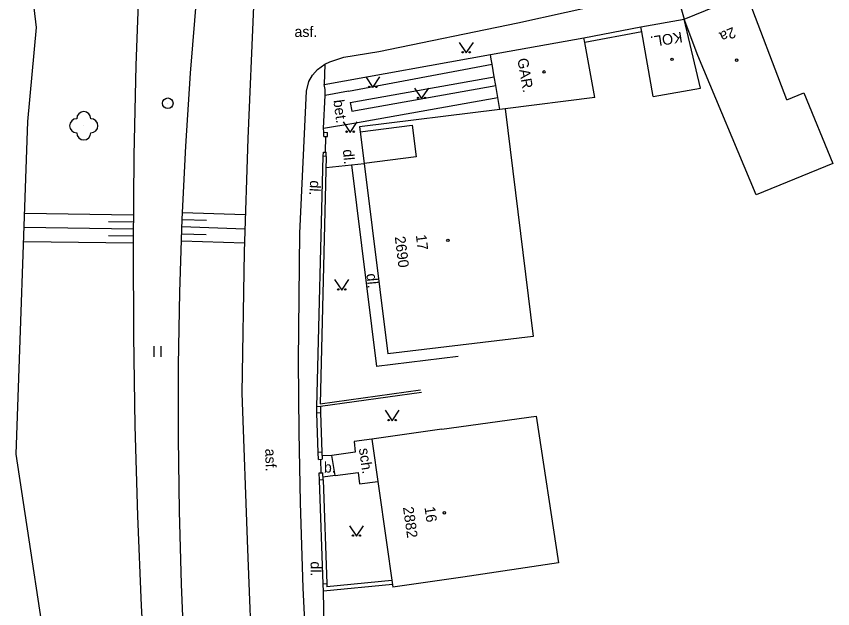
# Model space of a CAD drawing. Extents: x -584400 to -581602, y -1210894 to -1208793.
# Drawn here: x -583351.4 to -583293.7, y -1209655.4 to -1209613.5 of the extents above; entities that cross this region are included whole.
import ezdxf

# ---------------------------------------------------------------- set-up
doc = ezdxf.new("R2010")
doc.units = 0
for name, color, linetype in [('BUDOVY_MĚŘ', 7, 'Continuous'), ('BUDOVY_NEMĚŘ', 7, 'Continuous'), ('MAP_ZN_BP', 7, 'Continuous'), ('POMOC_POPIS', 7, 'Continuous'), ('ROZHRANÍ_PLOCH', 7, 'Continuous'), ('VÝŠKOPIS', 7, 'Continuous'), ('ZELEŇ', 7, 'Continuous'), ('ZN_BUDOV', 7, 'Continuous'), ('ZN_DOPLŇKOVÉ', 7, 'Continuous'), ('ZN_KULTUR', 7, 'Continuous'), ('Č_POPIS_EVID', 7, 'Continuous'), ('Č_POPIS_ORIENT', 7, 'Continuous')]:
    doc.layers.add(name, color=color, linetype=linetype)

msp = doc.modelspace()

# ---------------------------------------------------------------- linework, layer by layer
at = {"layer": 'BUDOVY_MĚŘ'}
for points in [[(-583304.16, -1209613.75), (-583299.75, -1209611.92)], [(-583306.36, -1209619.21), (-583307.16, -1209614.63), (-583307.22, -1209614.28), (-583304.16, -1209613.75)], [(-583303.19, -1209616.31), (-583304.16, -1209613.75)], [(-583317.19, -1209620.13), (-583317.34, -1209619.28), (-583317.49, -1209618.43), (-583317.6, -1209617.82), (-583317.74, -1209616.93), (-583317.8, -1209616.57), (-583317.86, -1209616.23), (-583311.25, -1209615.05)], [(-583310.49, -1209619.29), (-583311.19, -1209615.39), (-583311.25, -1209615.05)], [(-583310.49, -1209619.29), (-583316.82, -1209620.08), (-583317.19, -1209620.13)], [(-583317.19, -1209620.13), (-583327.11, -1209621.36), (-583327.07, -1209621.7), (-583326.79, -1209623.95), (-583325.12, -1209637.42)], [(-583316.82, -1209620.08), (-583314.84, -1209636.19), (-583325.12, -1209637.42)], [(-583327.07, -1209621.7), (-583323.4, -1209621.25), (-583323.12, -1209623.49), (-583326.79, -1209623.95)], [(-583321.3, -1209642.75), (-583326.25, -1209643.46), (-583324.76, -1209653.91)], [(-583319.81, -1209653.21), (-583324.76, -1209653.91)]]:
    msp.add_lwpolyline(points, dxfattribs=at)
at = {"layer": 'BUDOVY_NEMĚŘ'}
for points in [[(-583296.91, -1209619.44), (-583299.75, -1209611.92)], [(-583306.36, -1209619.21), (-583303.01, -1209618.63), (-583304.16, -1209613.75)], [(-583296.91, -1209619.44), (-583295.71, -1209618.95), (-583293.66, -1209623.95), (-583299.07, -1209626.16), (-583303.19, -1209616.31)], [(-583321.3, -1209642.75), (-583314.62, -1209641.83), (-583313.06, -1209652.19), (-583319.81, -1209653.21)]]:
    msp.add_lwpolyline(points, dxfattribs=at)
at = {"layer": 'MAP_ZN_BP'}
for radius in [0.375, 0.0005]:
    msp.add_circle((-583340.68, -1209619.691), radius, dxfattribs=at)
at = {"layer": 'ROZHRANÍ_PLOCH'}
for points in [[(-583322.44, -1209546.69), (-583325.37, -1209557.92), (-583329.4, -1209574.45), (-583329.82, -1209576.82), (-583331.22, -1209584.38), (-583332.92, -1209596.23), (-583333.98, -1209605.2), (-583334.42, -1209609.19), (-583334.48, -1209610.2), (-583334.58, -1209612.13), (-583335.13, -1209612.11), (-583335.13, -1209612.8), (-583334.62, -1209612.84), (-583335.02, -1209622.17), (-583335.28, -1209630.19), (-583335.44, -1209640.2), (-583335.04, -1209651.23), (-583334.69, -1209660.24)], [(-583348.69, -1209662.39), (-583351.39, -1209644.52), (-583350.57, -1209620.97), (-583349.96, -1209614.34), (-583351.26, -1209603.38), (-583349.77, -1209592.11), (-583348.74, -1209577.52), (-583341.06, -1209559.52)], [(-583329.58, -1209616.92), (-583329.21, -1209616.76), (-583328.23, -1209616.43), (-583325.75, -1209616.02), (-583315.92, -1209614), (-583309.09, -1209612.5), (-583304.81, -1209611.5), (-583304.16, -1209613.75)], [(-583330.81, -1209660.07), (-583331.11, -1209653.98), (-583331.29, -1209647.94), (-583331.4, -1209642.95), (-583331.44, -1209637.9), (-583331.33, -1209628.88), (-583330.87, -1209618.83), (-583330.71, -1209618.16), (-583330.45, -1209617.69), (-583330.1, -1209617.29), (-583329.58, -1209616.92)], [(-583329.58, -1209616.92), (-583329.61, -1209618.37)], [(-583327.89, -1209618.84), (-583317.74, -1209616.93)], [(-583327.78, -1209619.63), (-583317.6, -1209617.82)], [(-583327.89, -1209618.84), (-583329.56, -1209619.15), (-583329.54, -1209618.71)], [(-583327.78, -1209619.63), (-583327.66, -1209620.24), (-583317.49, -1209618.43)], [(-583329.67, -1209621.46), (-583329.56, -1209619.15)], [(-583329.67, -1209621.46), (-583327.52, -1209621.09), (-583317.34, -1209619.28)], [(-583329.64, -1209621.74), (-583329.67, -1209621.46)], [(-583329.49, -1209624.23), (-583327.68, -1209624.04)], [(-583327.68, -1209624.04), (-583326.79, -1209623.95)], [(-583327.68, -1209624.04), (-583325.91, -1209638.32)], [(-583320.14, -1209637.6), (-583325.91, -1209638.32)], [(-583329.07, -1209644.61), (-583329.77, -1209644.63)], [(-583328.84, -1209646.01), (-583329.07, -1209644.61)], [(-583328.84, -1209646.01), (-583329.71, -1209646.13)], [(-583329.62, -1209656.67), (-583329.66, -1209654.21)]]:
    msp.add_lwpolyline(points, dxfattribs=at)
at = {"layer": 'VÝŠKOPIS'}
for points in [[(-583342.71, -1209610.64), (-583342.93, -1209617.01), (-583343.07, -1209623.39), (-583343.13, -1209629.76), (-583343.11, -1209636.14), (-583343, -1209642.51), (-583342.82, -1209648.88), (-583342.56, -1209655.25), (-583342.04, -1209664.4)], [(-583339.18, -1209664.02), (-583339.49, -1209658.86), (-583339.72, -1209653.7), (-583339.86, -1209648.54), (-583339.93, -1209643.37), (-583339.92, -1209638.21), (-583339.83, -1209633.05), (-583339.66, -1209627.88), (-583339.41, -1209622.72), (-583339.07, -1209617.57), (-583338.61, -1209611.81)], [(-583350.8, -1209627.46), (-583343.12, -1209627.57)], [(-583335.2, -1209627.59), (-583339.64, -1209627.44)], [(-583344.86, -1209628.05), (-583343.12, -1209628.07)], [(-583337.94, -1209627.99), (-583339.66, -1209627.94)], [(-583350.83, -1209628.46), (-583343.12, -1209628.57)], [(-583335.23, -1209628.59), (-583339.68, -1209628.44)], [(-583344.88, -1209629.05), (-583343.13, -1209629.07)], [(-583337.96, -1209628.99), (-583339.7, -1209628.94)], [(-583350.87, -1209629.46), (-583343.13, -1209629.57)], [(-583335.26, -1209629.59), (-583339.72, -1209629.44)]]:
    msp.add_lwpolyline(points, dxfattribs=at)
at = {"layer": 'ZELEŇ'}
msp.add_circle((-583346.62, -1209621.28), 0.0005, dxfattribs=at)
for centre, start, end in [((-583346.62, -1209620.78), 0, 179.99999), ((-583347.12, -1209621.28), 89.99999, 269.99999), ((-583346.12, -1209621.28), 270, 89.99999), ((-583346.62, -1209621.78), 179.99999, 359.99999)]:
    msp.add_arc(centre, 0.5, start, end, dxfattribs=at)
at = {"layer": 'ZN_BUDOV'}
for centre in [(-583305.02, -1209616.58), (-583300.45, -1209616.64), (-583314.07, -1209617.47), (-583320.87, -1209629.38), (-583321.12, -1209648.66)]:
    msp.add_circle(centre, 0.0875, dxfattribs=at)
at = {"layer": 'ZN_DOPLŇKOVÉ'}
for points in [[(-583311.25, -1209615.05), (-583307.22, -1209614.28)], [(-583307.16, -1209614.63), (-583311.19, -1209615.39)], [(-583329.54, -1209618.71), (-583329.61, -1209618.37), (-583317.86, -1209616.23)], [(-583329.65, -1209622.04), (-583329.64, -1209621.74), (-583329.38, -1209621.75)], [(-583329.65, -1209622.04), (-583329.39, -1209622.05), (-583329.38, -1209621.75)], [(-583329.52, -1209622.04), (-583329.56, -1209623.15)], [(-583329.89, -1209641.14), (-583330.14, -1209641.17), (-583329.68, -1209623.44)], [(-583329.47, -1209623.45), (-583329.9, -1209640.94), (-583322.8, -1209639.96)], [(-583329.68, -1209623.44), (-583329.67, -1209623.15), (-583329.47, -1209623.15)], [(-583329.47, -1209623.45), (-583329.68, -1209623.44)], [(-583329.47, -1209623.45), (-583329.47, -1209623.15)], [(-583322.74, -1209640.16), (-583329.89, -1209641.14)], [(-583330.13, -1209641.6), (-583330.14, -1209641.17)], [(-583329.89, -1209641.14), (-583329.88, -1209641.59)], [(-583329.88, -1209641.59), (-583330.13, -1209641.6)], [(-583330.04, -1209644.39), (-583330.13, -1209641.6)], [(-583329.88, -1209641.59), (-583329.78, -1209644.38)], [(-583326.25, -1209643.46), (-583327.51, -1209643.61), (-583327.42, -1209644.36), (-583329.07, -1209644.61)], [(-583329.78, -1209644.38), (-583330.04, -1209644.39)], [(-583330.02, -1209644.88), (-583330.04, -1209644.39)], [(-583329.78, -1209644.38), (-583329.77, -1209644.87)], [(-583330.02, -1209644.88), (-583329.77, -1209644.87)], [(-583329.89, -1209644.88), (-583329.85, -1209645.84)], [(-583329.95, -1209646.34), (-583329.97, -1209645.84), (-583329.72, -1209645.83)], [(-583329.7, -1209646.33), (-583329.72, -1209645.83)], [(-583328.84, -1209646.01), (-583327.22, -1209645.81), (-583327.12, -1209646.61), (-583325.82, -1209646.45)], [(-583329.7, -1209646.33), (-583329.95, -1209646.34)], [(-583329.68, -1209653.7), (-583329.95, -1209646.34)], [(-583329.7, -1209646.33), (-583329.43, -1209653.69)], [(-583324.83, -1209653.45), (-583329.42, -1209653.9)], [(-583329.43, -1209653.69), (-583329.68, -1209653.7)], [(-583324.78, -1209653.74), (-583329.66, -1209654.21), (-583329.68, -1209653.7)], [(-583329.43, -1209653.69), (-583329.42, -1209653.9)]]:
    msp.add_lwpolyline(points, dxfattribs=at)
at = {"layer": 'ZN_KULTUR'}
for p, q in [((-583341.65, -1209637.625), (-583341.65, -1209636.875)), ((-583341.15, -1209637.625), (-583341.15, -1209636.875))]:
    msp.add_line(p, q, dxfattribs=at)
for points in [[(-583320.07, -1209615.38), (-583319.57, -1209616.13), (-583319.07, -1209615.38)], [(-583326.68, -1209617.83), (-583326.18, -1209618.58), (-583325.68, -1209617.83)], [(-583323.23, -1209618.61), (-583322.73, -1209619.36), (-583322.23, -1209618.61)], [(-583328.28, -1209621), (-583327.78, -1209621.75), (-583327.28, -1209621)], [(-583328.88, -1209632.16), (-583328.38, -1209632.91), (-583327.88, -1209632.16)], [(-583325.31, -1209641.4), (-583324.81, -1209642.15), (-583324.31, -1209641.4)], [(-583327.84, -1209649.57), (-583327.34, -1209650.32), (-583326.84, -1209649.57)]]:
    msp.add_lwpolyline(points, dxfattribs=at)
for centre in [(-583319.82, -1209616.08), (-583319.32, -1209616.08), (-583326.43, -1209618.53), (-583325.93, -1209618.53), (-583322.98, -1209619.31), (-583322.48, -1209619.31), (-583328.03, -1209621.7), (-583327.53, -1209621.7), (-583328.63, -1209632.86), (-583328.13, -1209632.86), (-583325.06, -1209642.1), (-583324.56, -1209642.1), (-583327.59, -1209650.27), (-583327.09, -1209650.27)]:
    msp.add_circle(centre, 0.05, dxfattribs=at)

# ---------------------------------------------------------------- texts
at = {"layer": 'POMOC_POPIS'}
for s, p in [('asf.', (-583331.72, -1209615)), ('b.', (-583329.64, -1209645.81))]:
    msp.add_text(s, height=0.75, dxfattribs=at).set_placement(p)
for s, rotation, p in [('KOL.', 188.86826, (-583304.35, -1209614.63)), ('GAR.', 279.7188, (-583315.96, -1209616.56)), ('bet.', 277.43144, (-583328.97, -1209619.48)), ('dl.', 275.19444, (-583328.3, -1209622.98)), ('dl.', 266.79207, (-583330.61, -1209625.13)), ('dl.', 275.19444, (-583326.63, -1209631.76)), ('asf.', 271.43721, (-583333.79, -1209644.13)), ('sch.', 278.28067, (-583327.17, -1209644.13)), ('dl.', 270, (-583330.58, -1209652.1))]:
    msp.add_text(s, height=0.75, rotation=rotation, dxfattribs=at).set_placement(p)
at = {"layer": 'Č_POPIS_EVID'}
for s, rotation, p in [('2690', 277.07494, (-583324.63, -1209629.14)), ('17', 277.07494, (-583323.14, -1209629.02)), ('2882', 278.09022, (-583324.05, -1209648.28)), ('16', 278.09022, (-583322.53, -1209648.27))]:
    msp.add_text(s, height=0.75, rotation=rotation, dxfattribs=at).set_placement(p)
at = {"layer": 'Č_POPIS_ORIENT'}
msp.add_text('2a', height=0.75, rotation=202.95408, dxfattribs=at).set_placement((-583300.71, -1209614.28))

doc.saveas('drawing.dxf')
